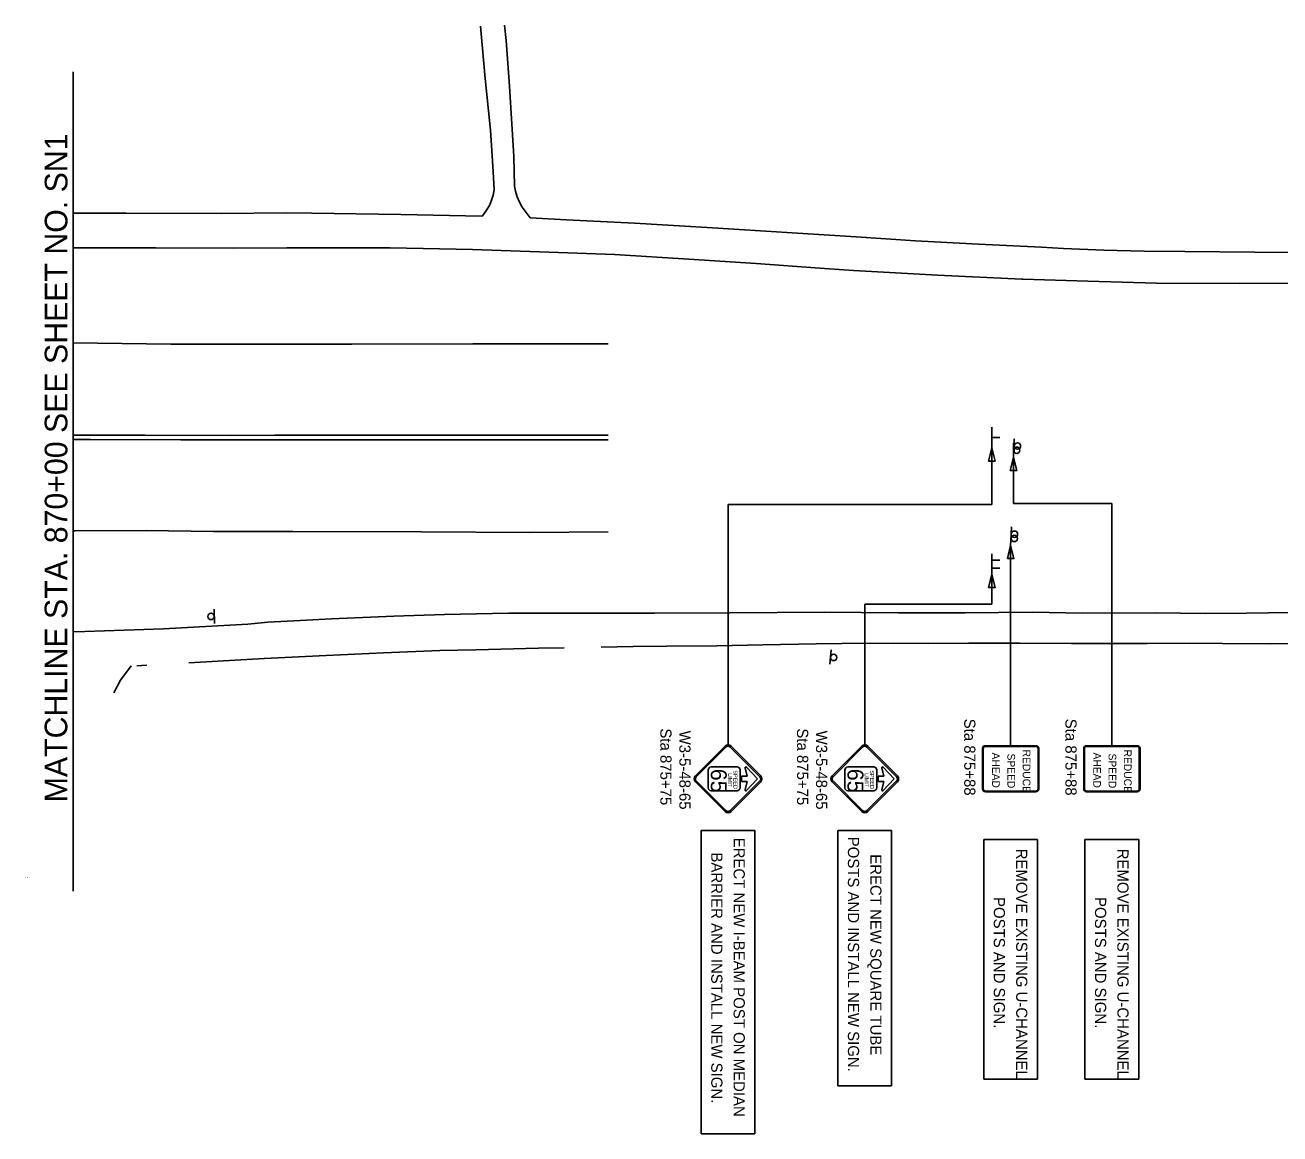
# Model space of a CAD drawing. Extents: x 1738774 to 1740361, y 1164458 to 1165341.
# Drawn here: x 1738774 to 1739559, y 1164458 to 1165152 of the extents above; entities that cross this region are included whole.
import ezdxf

# ---------------------------------------------------------------- set-up
doc = ezdxf.new("R2010")
doc.units = 0
for name, color, linetype in [('Default', 7, 'Continuous'), ('RD_EX_BldgApp', 7, 'Continuous'), ('RD_EX_Driveway', 7, 'Continuous'), ('RD_EX_Road', 7, 'Continuous'), ('RD_SHT_MatchLine', 7, 'Continuous'), ('RD_SHT_TX', 7, 'Continuous'), ('SN_P_Signs', 7, 'Continuous')]:
    doc.layers.add(name, color=color, linetype=linetype)

msp = doc.modelspace()

# ---------------------------------------------------------------- linework, layer by layer
at = {"layer": 'RD_EX_BldgApp'}
for points in [[(1739138.73, 1164895.48), (1739077.51, 1164895.55), (1738973.36, 1164895.58), (1738930.11, 1164895.42), (1738902.35, 1164895.38), (1738848.91, 1164895.6), (1738803.73, 1164895.53)], [(1738803.73, 1164892.75), (1738814.67, 1164892.76), (1738871.29, 1164892.53), (1738930.03, 1164892.57), (1739080.62, 1164892.68), (1739138.73, 1164892.61)]]:
    msp.add_lwpolyline(points, dxfattribs=at)
at = {"layer": 'RD_EX_Driveway'}
for points in [[(1739058.68, 1165151.47), (1739061.71, 1165118.87), (1739064.94, 1165086.35), (1739066.46, 1165063.85), (1739067.27, 1165049.22), (1739066.66, 1165045.82), (1739065.66, 1165042.52), (1739064.29, 1165039.35), (1739062.58, 1165036.36), (1739060.53, 1165033.58), (1739059.72, 1165032.65), (1739059.67, 1165032.59)], [(1739089.88, 1165031.47), (1739084.92, 1165038.31), (1739083.14, 1165041.44), (1739081.7, 1165044.75), (1739080.64, 1165048.2), (1739080.01, 1165051.4), (1739079.6, 1165069.87), (1739076.81, 1165114.07), (1739074.82, 1165142.48), (1739073.81, 1165152.21)]]:
    msp.add_lwpolyline(points, dxfattribs=at)
at = {"layer": 'RD_EX_Road'}
msp.add_line((1738849.87, 1164751.53), (1738843.63, 1164751.19), dxfattribs=at)
for points in [[(1739059.67, 1165032.65), (1739008.82, 1165033.61), (1738953.16, 1165034.46), (1738937.42, 1165034.61), (1738896.67, 1165034.22), (1738836.89, 1165034.44), (1738803.73, 1165034.42)], [(1739590.92, 1165009.82), (1739543.17, 1165009.96), (1739499.54, 1165010.39), (1739474.19, 1165010.66), (1739448.85, 1165011.32), (1739423.53, 1165012.38), (1739409.85, 1165013.11), (1739370.49, 1165014.97), (1739331.05, 1165017.22), (1739293.81, 1165019.7), (1739200.65, 1165025.47), (1739155.1, 1165028.16), (1739112.66, 1165030.4), (1739089.88, 1165031.47)], [(1738803.73, 1165012.79), (1738855.58, 1165012.83), (1738904.01, 1165012.6), (1738937.5, 1165012.8), (1739002.18, 1165012.72), (1739053.69, 1165011.69), (1739107.62, 1165009.77), (1739142.7, 1165008.52), (1739189.11, 1165005.63), (1739231.32, 1165002.96), (1739271.23, 1165000.11), (1739292.3, 1164998.59), (1739344.86, 1164995.66), (1739397.45, 1164993.12), (1739398.13, 1164993.09), (1739438.92, 1164991.81), (1739481.86, 1164990.75), (1739533.97, 1164990.4), (1739590.03, 1164990.67)], [(1738803.73, 1164953.24), (1738864.96, 1164952.37), (1738945.39, 1164952.57), (1738978.24, 1164952.46), (1739054, 1164952.71), (1739120.67, 1164952.61), (1739138.73, 1164952.72)], [(1738803.73, 1164835.53), (1738805.09, 1164835.55), (1738849.6, 1164835.75), (1738891.74, 1164835.25), (1738941.23, 1164835.23), (1739021.89, 1164835.07), (1739089.66, 1164834.66), (1739138.73, 1164834.96)], [(1738803.73, 1164772.43), (1738811.14, 1164772.61), (1738860.35, 1164774.22), (1738913.06, 1164777.3), (1738925.65, 1164778.35), (1738945.87, 1164779.46), (1738965.44, 1164780.44), (1739004.55, 1164782.14), (1739036.14, 1164783.18), (1739076.32, 1164784.12), (1739097.02, 1164784.07), (1739131.44, 1164784.02), (1739167.67, 1164784.09), (1739214.79, 1164784.35), (1739273.85, 1164784.74), (1739320.39, 1164784.34), (1739361.99, 1164784.34), (1739404.07, 1164784.65), (1739435.68, 1164784.15), (1739481.09, 1164784.25), (1739512.77, 1164783.82), (1739538.11, 1164784.14), (1739565.64, 1164784.49)], [(1739111.13, 1164762.41), (1739095.05, 1164762.14), (1739055.83, 1164761.21), (1739033.38, 1164760.69), (1738997.98, 1164759.22), (1738962.09, 1164757.56), (1738923.37, 1164755.73), (1738876.26, 1164752.98), (1738876.13, 1164752.97)], [(1739134.3, 1164762.8), (1739154.22, 1164763.17), (1739175.4, 1164763.38), (1739206.62, 1164763.53), (1739235.36, 1164764.33), (1739268.77, 1164764.95), (1739284.81, 1164764.99), (1739317.28, 1164765.27), (1739338.91, 1164764.99), (1739364.21, 1164765.38), (1739396.31, 1164765.27), (1739428.64, 1164765.1), (1739476.04, 1164765.15), (1739502.33, 1164765.23), (1739523.17, 1164765), (1739552.94, 1164764.93), (1739583.93, 1164765.19)], [(1738829.24, 1164734.11), (1738833.47, 1164742.2), (1738840.11, 1164751.07), (1738840.18, 1164751.18)]]:
    msp.add_lwpolyline(points, dxfattribs=at)
at = {"layer": 'RD_SHT_MatchLine'}
msp.add_lwpolyline([(1738803.73, 1164609.99), (1738803.73, 1164894.04), (1738803.73, 1165122.99)], dxfattribs=at)
at = {"layer": 'SN_P_Signs'}
for p, q in [((1739378.73, 1164887.52), (1739378.73, 1164900.56)), ((1739378.73, 1164852.16), (1739378.73, 1164894.04)), ((1739378.73, 1164894.04), (1739383.72, 1164894.04)), ((1739392.27, 1164890.57), (1739392.36, 1164881.57)), ((1739392.74, 1164893.22), (1739392.83, 1164884.22)), ((1739392.36, 1164852.79), (1739392.36, 1164881.57)), ((1739213.71, 1164701.53), (1739213.71, 1164852.16)), ((1739378.73, 1164852.16), (1739213.71, 1164852.16)), ((1739453.88, 1164852.79), (1739392.36, 1164852.79)), ((1739453.88, 1164701.09), (1739453.88, 1164852.79)), ((1739391.07, 1164835.48), (1739390.55, 1164826.5)), ((1739391.11, 1164838.11), (1739390.7, 1164829.12)), ((1739390.55, 1164701.09), (1739390.55, 1164826.5)), ((1739378.73, 1164808.27), (1739378.73, 1164821.31)), ((1739378.73, 1164817.2), (1739383.72, 1164817.2)), ((1739378.73, 1164812.18), (1739383.72, 1164812.18)), ((1739378.73, 1164789.64), (1739378.73, 1164808.27)), ((1738892.27, 1164777.57), (1738891.98, 1164786.57)), ((1739299.25, 1164701.53), (1739299.25, 1164789.64)), ((1739378.73, 1164789.64), (1739299.25, 1164789.64)), ((1739278.19, 1164761.05), (1739277.39, 1164752.08)), ((1739193.29, 1164682.2), (1739211.86, 1164700.76)), ((1739215.57, 1164700.76), (1739234.13, 1164682.2)), ((1739278.84, 1164682.2), (1739297.4, 1164700.76)), ((1739301.11, 1164700.76), (1739319.67, 1164682.2)), ((1739372.91, 1164674.09), (1739372.91, 1164699.29)), ((1739374.71, 1164701.09), (1739406.38, 1164701.09)), ((1739374.71, 1164700.64), (1739406.38, 1164700.64)), ((1739408.18, 1164699.29), (1739408.18, 1164674.09)), ((1739436.25, 1164674.09), (1739436.25, 1164699.29)), ((1739438.05, 1164701.09), (1739469.71, 1164701.09)), ((1739438.05, 1164700.64), (1739469.71, 1164700.64)), ((1739471.51, 1164699.29), (1739471.51, 1164674.09)), ((1739201.21, 1164674.72), (1739201.21, 1164685.97)), ((1739203.09, 1164687.85), (1739219.34, 1164687.85)), ((1739221.21, 1164685.97), (1739221.21, 1164674.72)), ((1739222.05, 1164678.72), (1739222.05, 1164681.97)), ((1739222.05, 1164681.97), (1739225.55, 1164681.97)), ((1739225.55, 1164681.97), (1739224.32, 1164687.2)), ((1739225.17, 1164687.65), (1739232.05, 1164680.35)), ((1739286.75, 1164674.72), (1739286.75, 1164685.97)), ((1739288.63, 1164687.85), (1739304.88, 1164687.85)), ((1739306.76, 1164685.97), (1739306.76, 1164674.72)), ((1739307.59, 1164678.72), (1739307.59, 1164681.97)), ((1739307.59, 1164681.97), (1739311.09, 1164681.97)), ((1739311.09, 1164681.97), (1739309.86, 1164687.2)), ((1739310.71, 1164687.65), (1739317.59, 1164680.35)), ((1739211.86, 1164659.93), (1739193.29, 1164678.49)), ((1739234.13, 1164678.49), (1739215.57, 1164659.93)), ((1739225.55, 1164678.72), (1739222.05, 1164678.72)), ((1739224.32, 1164673.5), (1739225.55, 1164678.72)), ((1739232.05, 1164680.35), (1739225.17, 1164673.04)), ((1739297.4, 1164659.93), (1739278.84, 1164678.49)), ((1739319.67, 1164678.49), (1739301.11, 1164659.93)), ((1739311.09, 1164678.72), (1739307.59, 1164678.72)), ((1739309.86, 1164673.5), (1739311.09, 1164678.72)), ((1739317.59, 1164680.35), (1739310.71, 1164673.04)), ((1739219.34, 1164672.85), (1739203.09, 1164672.85)), ((1739304.88, 1164672.85), (1739288.63, 1164672.85)), ((1739406.38, 1164672.29), (1739374.71, 1164672.29)), ((1739469.71, 1164672.29), (1739438.05, 1164672.29)), ((1739196.9, 1164458.1), (1739196.9, 1164648.12)), ((1739196.9, 1164648.12), (1739230.52, 1164648.12)), ((1739230.52, 1164648.12), (1739230.52, 1164458.1)), ((1739282.45, 1164488.1), (1739282.45, 1164648.12)), ((1739282.45, 1164648.12), (1739316.06, 1164648.12)), ((1739316.06, 1164648.12), (1739316.06, 1164488.1)), ((1739373.74, 1164492.36), (1739373.74, 1164642.38)), ((1739373.74, 1164642.38), (1739407.36, 1164642.38)), ((1739407.36, 1164642.38), (1739407.36, 1164492.36)), ((1739437.07, 1164492.36), (1739437.07, 1164642.38)), ((1739437.07, 1164642.38), (1739470.69, 1164642.38)), ((1739470.69, 1164642.38), (1739470.69, 1164492.36)), ((1739316.06, 1164488.1), (1739282.45, 1164488.1)), ((1739407.36, 1164492.36), (1739373.74, 1164492.36)), ((1739470.69, 1164492.36), (1739437.07, 1164492.36)), ((1739230.52, 1164458.1), (1739196.9, 1164458.1))]:
    msp.add_line(p, q, dxfattribs=at)
for points in [[(1739376.68, 1164879.32), (1739378.73, 1164887.52), (1739380.79, 1164879.32)], [(1739390.31, 1164873.37), (1739392.36, 1164881.57), (1739394.41, 1164873.37)], [(1739388.5, 1164818.3), (1739390.55, 1164826.5), (1739392.6, 1164818.3)], [(1739376.68, 1164800.07), (1739378.73, 1164808.27), (1739380.79, 1164800.07)]]:
    msp.add_lwpolyline(points, close=True, dxfattribs=at)
for points in [[(1739193.82, 1164681.67), (1739212.39, 1164700.23)], [(1739215.04, 1164700.23), (1739233.6, 1164681.67)], [(1739279.37, 1164681.67), (1739297.93, 1164700.23)], [(1739300.58, 1164700.23), (1739319.14, 1164681.67)], [(1739373.36, 1164674.09), (1739373.36, 1164699.29)], [(1739407.73, 1164699.29), (1739407.73, 1164674.09)], [(1739436.7, 1164674.09), (1739436.7, 1164699.29)], [(1739471.06, 1164699.29), (1739471.06, 1164674.09)], [(1739212.39, 1164660.46), (1739193.82, 1164679.02)], [(1739233.6, 1164679.02), (1739215.04, 1164660.46)], [(1739297.93, 1164660.46), (1739279.37, 1164679.02)], [(1739319.14, 1164679.02), (1739300.58, 1164660.46)], [(1739406.38, 1164672.74), (1739374.71, 1164672.74)], [(1739469.71, 1164672.74), (1739438.05, 1164672.74)]]:
    msp.add_lwpolyline(points, dxfattribs=at)
for centre in [(1739394.34, 1164886.07), (1739394.81, 1164888.72), (1739392.83, 1164830.86), (1739392.92, 1164833.51), (1738890.1, 1164782.02), (1739279.8, 1164756.37)]:
    msp.add_circle(centre, 2, dxfattribs=at)
for centre, radius, start, end in [((1739213.71, 1164698.91), 2.63, 45, 135), ((1739213.71, 1164698.91), 1.88, 45, 135), ((1739299.25, 1164698.91), 2.63, 45, 135), ((1739299.25, 1164698.91), 1.88, 45, 135), ((1739374.71, 1164699.29), 1.8, 90, 180), ((1739374.71, 1164699.29), 1.35, 90, 180), ((1739406.38, 1164699.29), 1.8, 0, 90), ((1739406.38, 1164699.29), 1.35, 0, 90), ((1739438.05, 1164699.29), 1.8, 90, 180), ((1739438.05, 1164699.29), 1.35, 90, 180), ((1739469.71, 1164699.29), 1.8, 0, 90), ((1739469.71, 1164699.29), 1.35, 0, 90), ((1739195.15, 1164680.35), 2.63, 135, 225), ((1739203.09, 1164685.97), 1.88, 90, 180), ((1739219.34, 1164685.97), 1.88, 360, 90), ((1739224.81, 1164687.31), 0.5, 43.2643, 193.24052), ((1739232.27, 1164680.35), 2.63, 315, 45), ((1739280.69, 1164680.35), 2.63, 135, 225), ((1739288.63, 1164685.97), 1.88, 90, 180), ((1739304.88, 1164685.97), 1.88, 360, 90), ((1739310.35, 1164687.31), 0.5, 43.2643, 193.24052), ((1739317.82, 1164680.35), 2.63, 315, 45), ((1739195.15, 1164680.35), 1.88, 135, 225), ((1739203.09, 1164674.72), 1.88, 180, 270), ((1739219.34, 1164674.72), 1.88, 270, 360), ((1739232.27, 1164680.35), 1.88, 315, 45), ((1739280.69, 1164680.35), 1.88, 135, 225), ((1739288.63, 1164674.72), 1.88, 180, 270), ((1739304.88, 1164674.72), 1.88, 270, 360), ((1739317.82, 1164680.35), 1.88, 315, 45), ((1739374.71, 1164674.09), 1.8, 180, 270), ((1739374.71, 1164674.09), 1.35, 180, 270), ((1739406.38, 1164674.09), 1.35, 270, 0), ((1739406.38, 1164674.09), 1.8, 270, 0), ((1739438.05, 1164674.09), 1.8, 180, 270), ((1739438.05, 1164674.09), 1.35, 180, 270), ((1739469.71, 1164674.09), 1.35, 270, 0), ((1739469.71, 1164674.09), 1.8, 270, 0), ((1739224.81, 1164673.38), 0.5, 166.75948, 316.7357), ((1739310.35, 1164673.38), 0.5, 166.75948, 316.7357), ((1739213.71, 1164661.78), 2.63, 225, 315), ((1739213.71, 1164661.78), 1.88, 225, 315), ((1739299.25, 1164661.78), 2.63, 225, 315), ((1739299.25, 1164661.78), 1.88, 225, 315)]:
    msp.add_arc(centre, radius, start, end, dxfattribs=at)

# ---------------------------------------------------------------- texts
at = {"layer": 'Default'}
for s, height, p in [('Sheet: 2', 0.208, (1738773.73, 1164618.83)), ('Angle:  16.0848', 0.2083, (1738773.73, 1164618.56)), ('Align: A_I85', 0.2083, (1738773.73, 1164618.29))]:
    msp.add_text(s, height=height, dxfattribs=at).set_placement(p)
at = {"layer": 'RD_SHT_TX'}
msp.add_text('MATCHLINE STA. 870+00 SEE SHEET NO. SN1', height=14.1726, rotation=89.98556, dxfattribs=at).set_placement((1738800.14, 1164665.67))
at = {"layer": 'SN_P_Signs'}
for s, height, rotation, p in [('Sta 875+88', 7, 270.00008, (1739361.49, 1164718.02)), ('Sta 875+88', 7, 270.00008, (1739424.83, 1164718.02)), ('Sta 875+75', 7, 270.00008, (1739171.29, 1164711.98)), ('W3-5-48-65', 7, 270.00008, (1739183.19, 1164710.55)), ('Sta 875+75', 7, 270.00008, (1739256.84, 1164711.98)), ('W3-5-48-65', 7, 270.00008, (1739268.74, 1164710.55)), ('REDUCE', 4.8, 270, (1739398.12, 1164698.67)), ('REDUCE', 4.8, 270, (1739461.45, 1164698.67)), ('AHEAD', 4.8, 270, (1739378.92, 1164696.83)), ('SPEED', 4.8, 270, (1739388.52, 1164696.21)), ('AHEAD', 4.8, 270, (1739442.25, 1164696.83)), ('SPEED', 4.8, 270, (1739451.85, 1164696.21)), ('65', 10, 270, (1739202.88, 1164686.66)), ('LIMIT', 2.5, 270, (1739213.71, 1164683.97)), ('SPEED', 2.5, 270, (1739217.05, 1164685.7)), ('65', 10, 270, (1739288.42, 1164686.66)), ('LIMIT', 2.5, 270, (1739299.25, 1164683.97)), ('SPEED', 2.5, 270, (1739302.59, 1164685.7)), ('ERECT NEW I-BEAM POST ON MEDIAN ', 6.9998, 270.00008, (1739217.16, 1164643.56)), ('POSTS AND INSTALL NEW SIGN.', 6.9998, 270.00008, (1739288.7, 1164644.14)), ('REMOVE EXISTING U-CHANNEL', 6.9998, 270.00008, (1739393.99, 1164636.65)), ('REMOVE EXISTING U-CHANNEL', 6.9998, 270.00008, (1739457.33, 1164636.65)), ('BARRIER AND INSTALL NEW SIGN.', 6.9998, 270.00008, (1739203.16, 1164634.3)), ('ERECT NEW SQUARE TUBE', 6.9998, 270.00008, (1739302.7, 1164633.16)), ('POSTS AND SIGN.', 6.9998, 270.00008, (1739379.99, 1164606.39)), ('POSTS AND SIGN.', 6.9998, 270.00008, (1739443.33, 1164606.39))]:
    msp.add_text(s, height=height, rotation=rotation, dxfattribs=at).set_placement(p)

doc.saveas('drawing.dxf')
